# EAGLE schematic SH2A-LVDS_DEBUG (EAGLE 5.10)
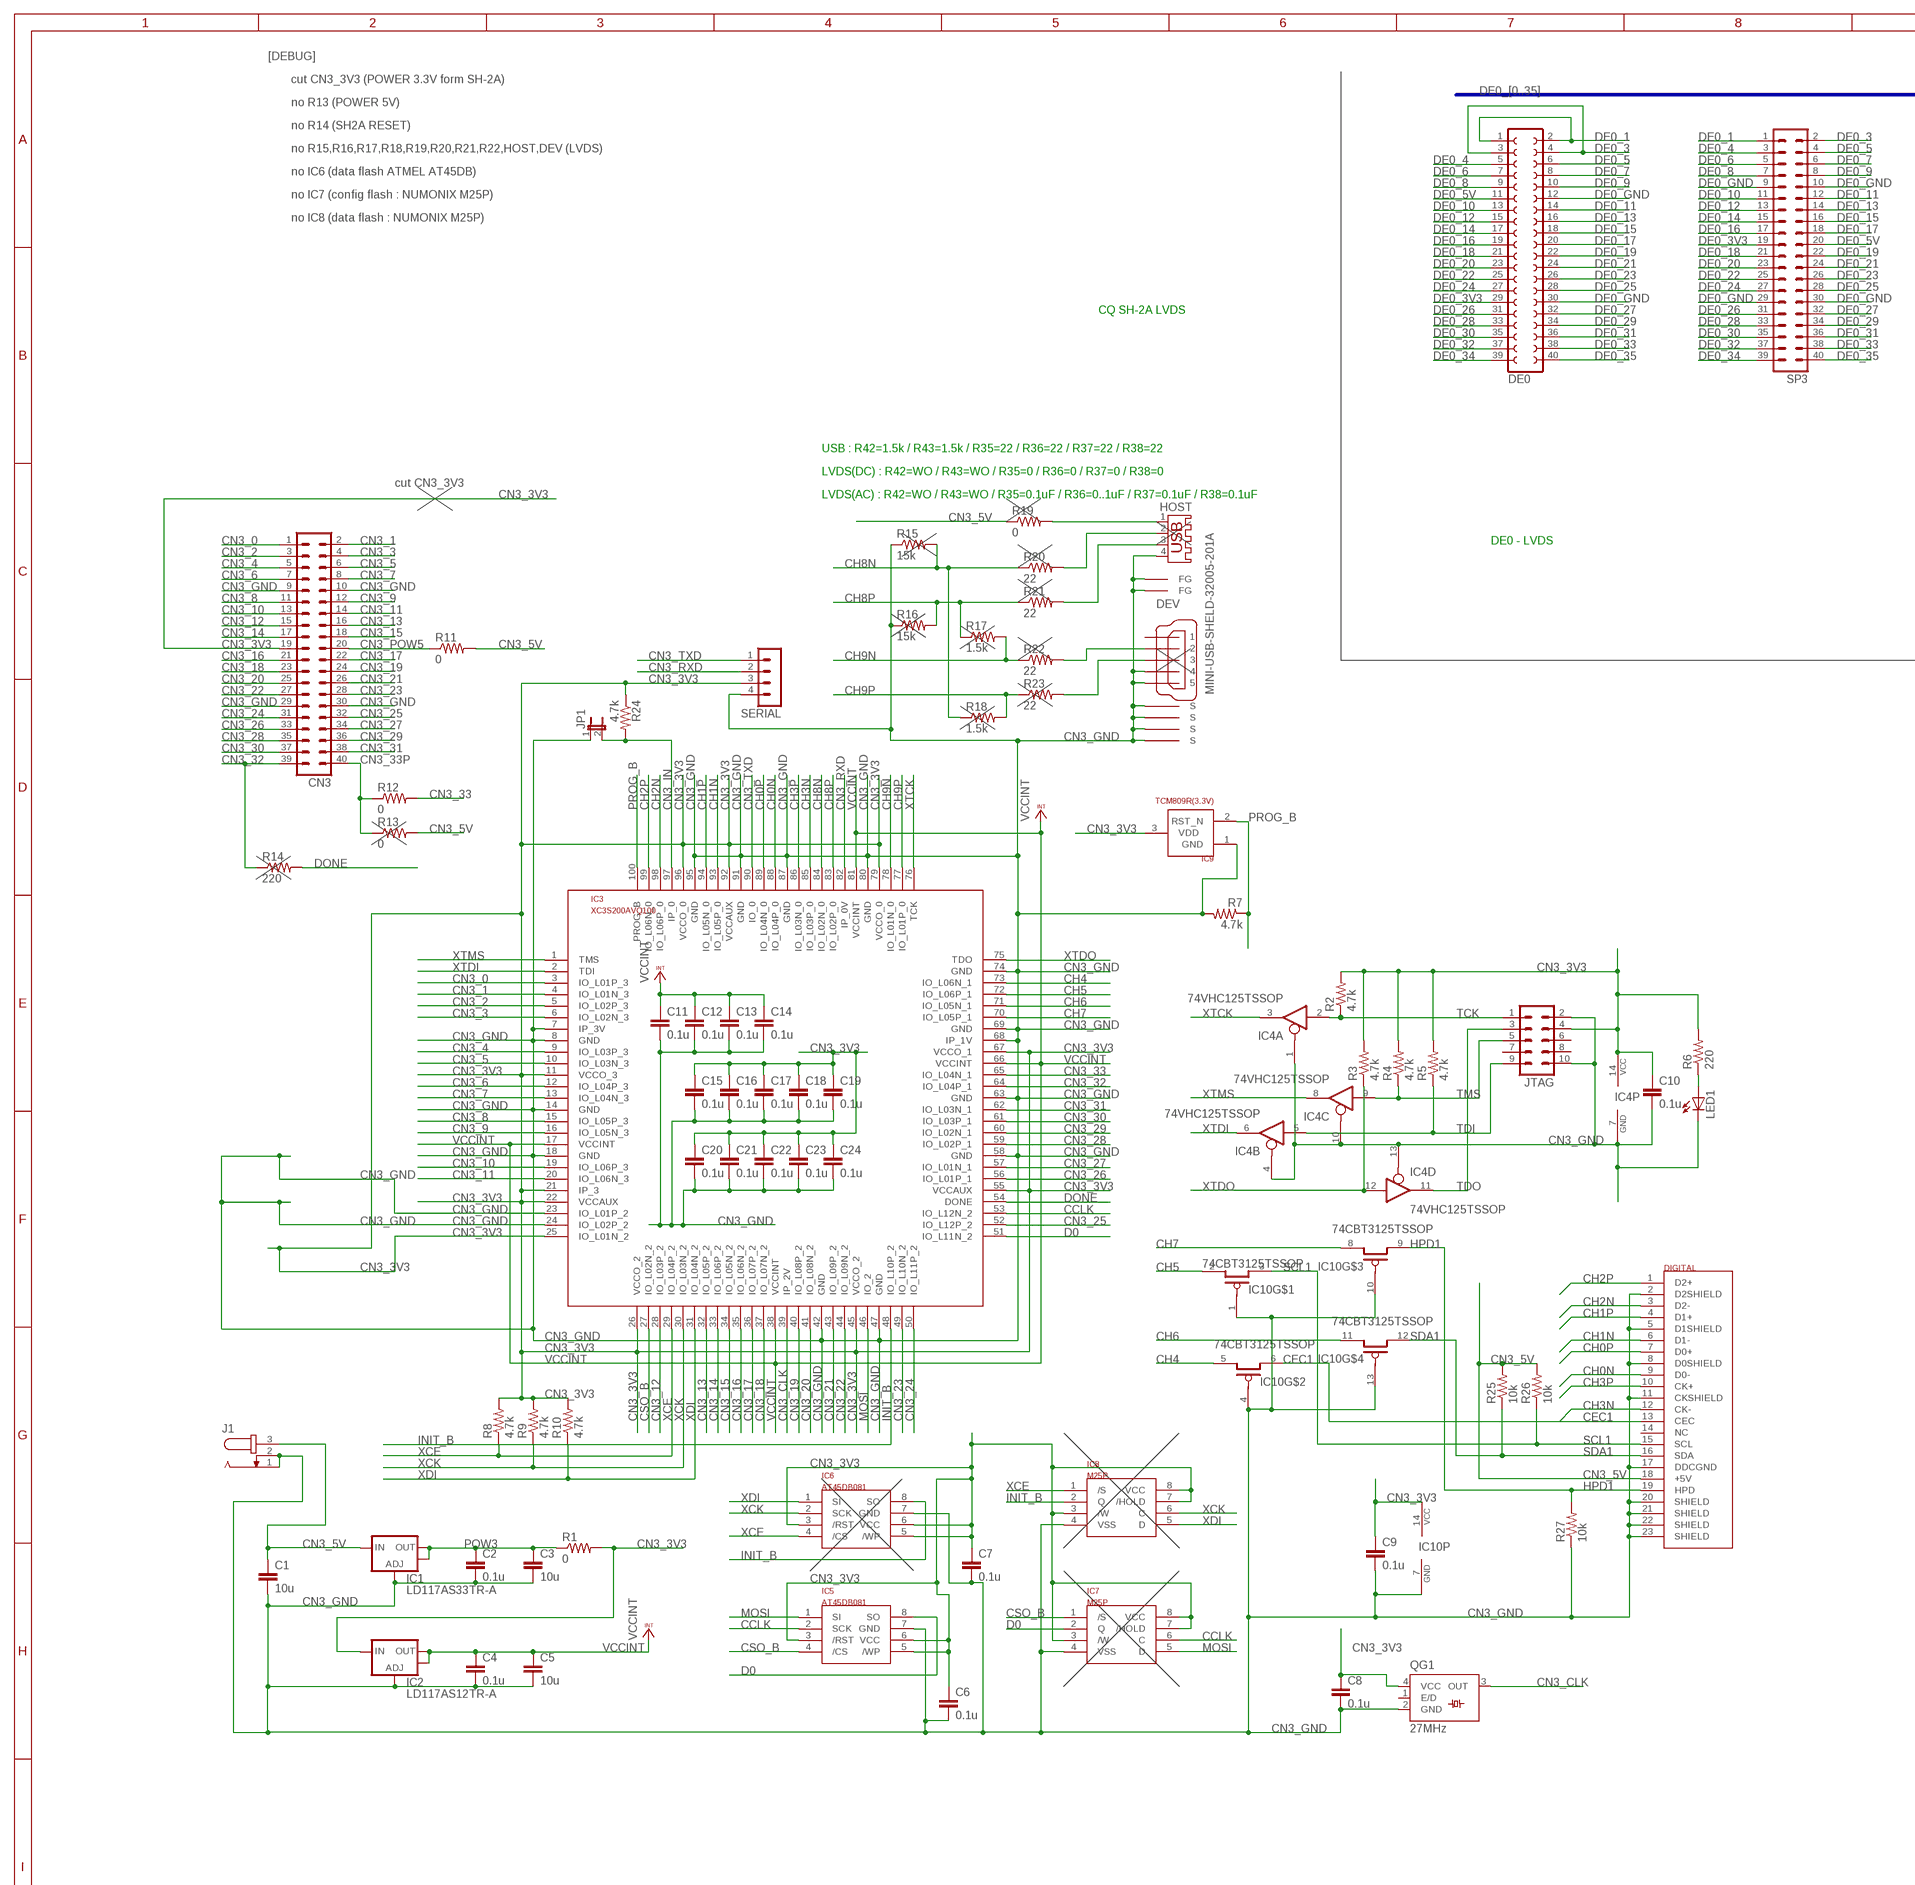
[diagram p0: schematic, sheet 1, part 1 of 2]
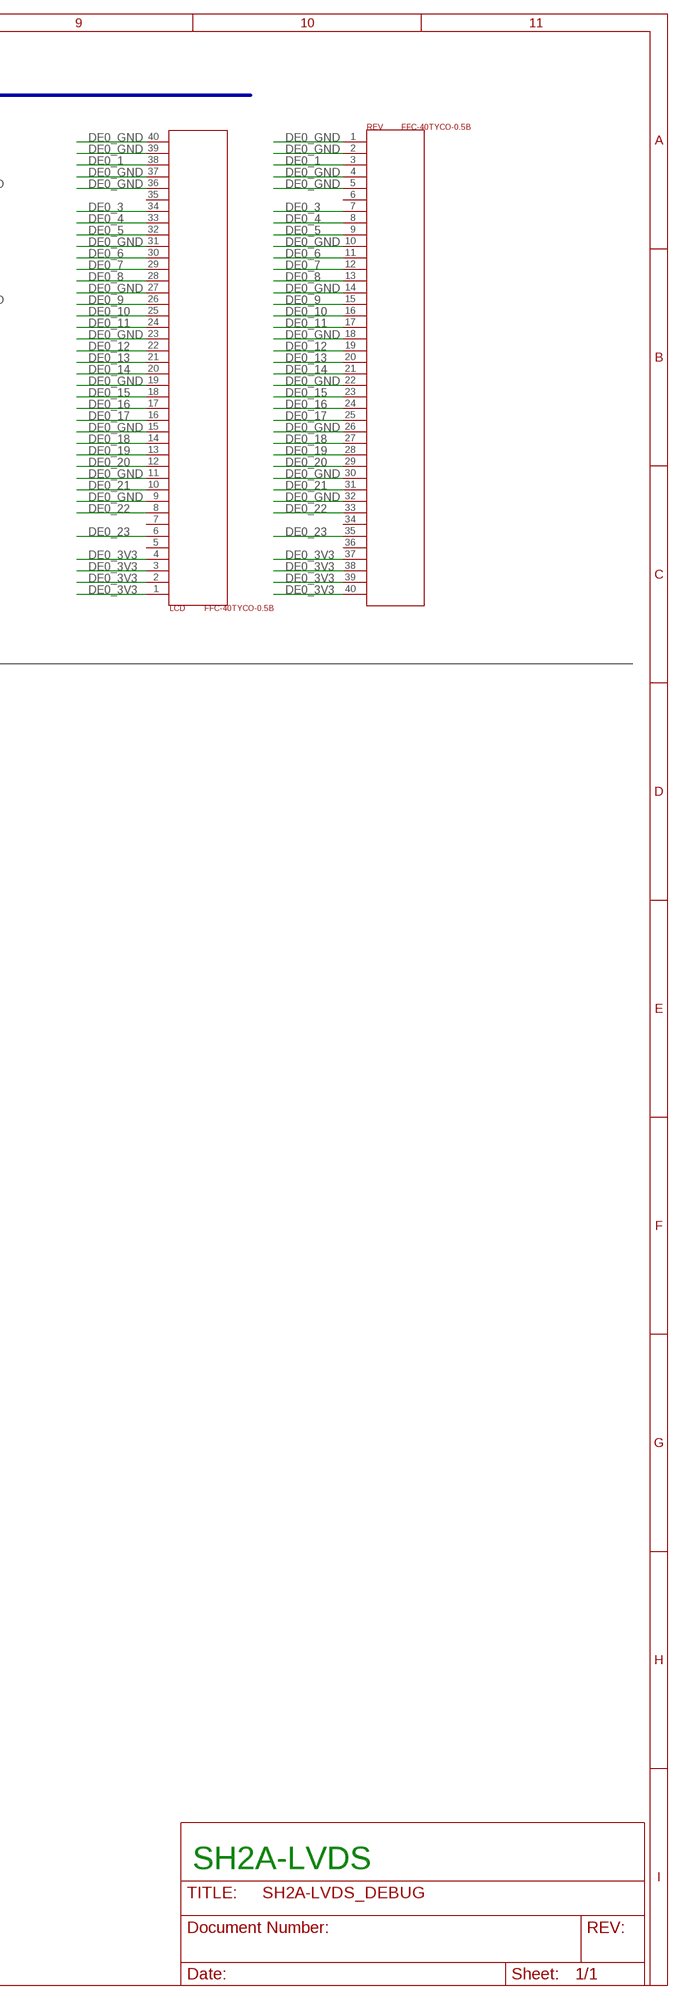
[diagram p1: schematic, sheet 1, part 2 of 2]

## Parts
C1  10u  C-EUC2012  [C2012]
C2  0.1u  C-EUC1608  [C1608]
C3  10u  C-EUC2012  [C2012]
C4  0.1u  C-EUC1608  [C1608]
C5  10u  C-EUC2012  [C2012]
C6  0.1u  C-EUC1608  [C1608]
C7  0.1u  C-EUC1608  [C1608]
C8  0.1u  C-EUC1608  [C1608]
C9  0.1u  C-EUC1608  [C1608]
C10  0.1u  C-EUC1608  [C1608]
C11  0.1u  C-EUC1608  [C1608]
C12  0.1u  C-EUC1608  [C1608]
C13  0.1u  C-EUC1608  [C1608]
C14  0.1u  C-EUC1608  [C1608]
C15  0.1u  C-EUC1608  [C1608]
C16  0.1u  C-EUC1608  [C1608]
C17  0.1u  C-EUC1608  [C1608]
C18  0.1u  C-EUC1608  [C1608]
C19  0.1u  C-EUC1608  [C1608]
C20  0.1u  C-EUC1608  [C1608]
C21  0.1u  C-EUC1608  [C1608]
C22  0.1u  C-EUC1608  [C1608]
C23  0.1u  C-EUC1608  [C1608]
C24  0.1u  C-EUC1608  [C1608]
CN3  MA20-2  [MA20-2]
DE0  FE20-2  [FE20-2]
DEV  MINI-USB-SHELD-32005-201A  [32005-201A]
DIGITAL  HDMIHDMI-FCI-A  [HDMI-FCI-A-UPDATE]
HOST  USB-A003FG  [USB]
IC1  LD117AS33TR-A  LD117AS-A  [SOT223]
IC2  LD117AS12TR-A  LD117AS-A  [SOT223]
IC3  XC3S200AVQ100  XC3S50AVQ100  [VQ100]
IC4  74VHC125TSSOP  74125TSSOP  [PW_R-PDSO-G14]
IC5  AT45DB081  AT45DB  [AT45DB]
IC6  AT45DB081  AT45DB  [AT45DB]
IC7  M25P  [AT45DB]
IC8  M25P  [AT45DB]
IC9  TCM809R(3.3V)  TCM809  [SOT23]
IC10  74CBT3125TSSOP  [PW_R-PDSO-G14]
J1  JACK-PLUG0A  [SPC4077A]
JP1  JP1EA  [JP1A]
JTAG  ML10  [ML10]
LCD  FFC-40TYCO-0.5B  [FFC-40-0.5B-TYCO]
LED1  LED5MM  [LED5MM]
QG1  27MHz  SM77H  [SM77H]
R1  0  R-US_R0603  [R0603]
R2  4.7k  R-US_R0603  [R0603]
R3  4.7k  R-US_R0603  [R0603]
R4  4.7k  R-US_R0603  [R0603]
R5  4.7k  R-US_R0603  [R0603]
R6  220  R-US_R0603  [R0603]
R7  4.7k  R-US_R0603  [R0603]
R8  4.7k  R-US_R0603  [R0603]
R9  4.7k  R-US_R0603  [R0603]
R10  4.7k  R-US_R0603  [R0603]
R11  0  R-US_R0603  [R0603]
R12  0  R-US_R0603  [R0603]
R13  0  R-US_R0603  [R0603]
R14  220  R-US_R0603  [R0603]
R15  15k  R-US_R0603  [R0603]
R16  15k  R-US_R0603  [R0603]
R17  1.5k  R-US_R0603  [R0603]
R18  1.5k  R-US_R0603  [R0603]
R19  0  R-US_R0603  [R0603]
R20  22  R-US_R0603  [R0603]
R21  22  R-US_R0603  [R0603]
R22  22  R-US_R0603  [R0603]
R23  22  R-US_R0603  [R0603]
R24  4.7k  R-US_R0603  [R0603]
R25  10k  R-US_R0603  [R0603]
R26  10k  R-US_R0603  [R0603]
R27  10k  R-US_R0603  [R0603]
REV  FFC-40TYCO-0.5B  [FFC-40-0.5B-TYCO]
SERIAL  MA04-1A  [MA04-1A]
SP3  MA20-2  [MA20-2]

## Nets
CCLK: IC3.53(IO_L12N_2) IC5.2(SCK) IC7.6(C)
CEC1: DIGITAL.13(CEC) IC10.6(O)
CH0N: DIGITAL.9(D0-) IC3.88(IO_L04P_0)
CH0P: DIGITAL.7(D0+) IC3.89(IO_L04N_0)
CH1N: DIGITAL.6(D1-) IC3.93(IO_L05P_0)
CH1P: DIGITAL.4(D1+) IC3.94(IO_L05N_0)
CH2N: DIGITAL.3(D2-) IC3.98(IO_L06P_0)
CH2P: DIGITAL.1(D2+) IC3.99(IO_L06N_0)
CH3N: DIGITAL.12(CK-) IC3.85(IO_L03P_0)
CH3P: DIGITAL.10(CK+) IC3.86(IO_L03N_0)
CH4: IC3.73(IO_L06N_1) IC10.5(I)
CH5: IC3.72(IO_L06P_1) IC10.2(I)
CH6: IC3.71(IO_L05N_1) IC10.11(O)
CH7: IC3.70(IO_L05P_1) IC10.8(O)
CH8N: IC3.84(IO_L02N_0) R15.2 R18.1 R20.1
CH8P: IC3.83(IO_L02P_0) R16.2 R17.1 R21.1
CH9N: IC3.78(IO_L01N_0) R17.2 R22.1
CH9P: IC3.77(IO_L01P_0) R18.2 R23.1
CN3_0: CN3.1 IC3.3(IO_L01P_3)
CN3_1: CN3.2 IC3.4(IO_L01N_3)
CN3_2: CN3.3 IC3.5(IO_L02P_3)
CN3_3: CN3.4 IC3.6(IO_L02N_3)
CN3_3V3: C6.1 C7.1 C8.1 C9.1 C10.1 C15.1 C16.1 C17.1 C18.1 C19.1 C20.1 C21.1 C22.1 C23.1 C24.1 CN3.19 IC2.3(IN) IC3.11(VCCO_3) IC3.21(IP_3) IC3.22(VCCAUX) IC3.25(IO_L01N_2) IC3.26(VCCO_2) IC3.45(VCCO_2) IC3.55(VCCAUX) IC3.67(VCCO_1) IC3.79(VCCO_0) IC3.92(VCCAUX) IC3.96(VCCO_0) IC4.14(P:VCC) IC5.3(/RST) IC5.5(/WP) IC5.6(VCC) IC6.3(/RST) IC6.5(/WP) IC6.6(VCC) IC7.3(/W) IC7.7(/HOLD) IC7.8(VCC) IC8.3(/W) IC8.7(/HOLD) IC8.8(VCC) IC9.3(VDD) IC10.14(P:VCC) JTAG.4 QG1.4(VCC) R1.2 R2.2 R3.2 R4.2 R5.2 R6.2 R8.2 R9.2 R10.2 R24.1 SERIAL.3
CN3_4: CN3.5 IC3.9(IO_L03P_3)
CN3_5: CN3.6 IC3.10(IO_L03N_3)
CN3_5V: C1.1 DIGITAL.18(+5V) IC1.3(IN) J1.3 R11.2 R13.2 R19.1 R25.2 R26.2
CN3_6: CN3.7 IC3.12(IO_L04P_3)
CN3_7: CN3.8 IC3.13(IO_L04N_3)
CN3_8: CN3.11 IC3.15(IO_L05P_3)
CN3_9: CN3.12 IC3.16(IO_L05N_3)
CN3_10: CN3.13 IC3.19(IO_L06P_3)
CN3_11: CN3.14 IC3.20(IO_L06N_3)
CN3_12: CN3.15 IC3.28(IO_L03P_2)
CN3_13: CN3.16 IC3.32(IO_L05P_2)
CN3_14: CN3.17 IC3.33(IO_L06P_2)
CN3_15: CN3.18 IC3.34(IO_L05N_2)
CN3_16: CN3.21 IC3.35(IO_L06N_2)
CN3_17: CN3.22 IC3.36(IO_L07P_2)
CN3_18: CN3.23 IC3.37(IO_L07N_2)
CN3_19: CN3.24 IC3.40(IO_L08P_2)
CN3_20: CN3.25 IC3.41(IO_L08N_2)
CN3_21: CN3.26 IC3.43(IO_L09P_2)
CN3_22: CN3.27 IC3.44(IO_L09N_2)
CN3_23: CN3.28 IC3.49(IO_L10N_2)
CN3_24: CN3.31 IC3.50(IO_L11P_2)
CN3_25: CN3.32 IC3.52(IO_L12P_2)
CN3_26: CN3.33 IC3.56(IO_L01P_1)
CN3_27: CN3.34 IC3.57(IO_L01N_1)
CN3_28: CN3.35 IC3.59(IO_L02P_1)
CN3_29: CN3.36 IC3.60(IO_L02N_1)
CN3_30: CN3.37 IC3.61(IO_L03P_1)
CN3_31: CN3.38 IC3.62(IO_L03N_1)
CN3_32: CN3.39 IC3.64(IO_L04P_1) R14.1
CN3_33: IC3.65(IO_L04N_1) R12.2
CN3_33P: CN3.40 R12.1 R13.1
CN3_CLK: IC3.39(IP_2V) QG1.3(OUT)
CN3_GND: C1.2 C2.2 C3.2 C4.2 C5.2 C6.2 C7.2 C8.2 C9.2 C10.2 C11.2 C12.2 C13.2 C14.2 C15.2 C16.2 C17.2 C18.2 C19.2 C20.2 C21.2 C22.2 C23.2 C24.2 CN3.9 CN3.10 CN3.29 CN3.30 DEV.4 DEV.5 DEV.M1(S) DEV.M2(S) DEV.M3(S) DEV.M4(S) DIGITAL.2(D2SHIELD) DIGITAL.5(D1SHIELD) DIGITAL.8(D0SHIELD) DIGITAL.11(CKSHIELD) DIGITAL.17(DDCGND) DIGITAL.20(SHIELD) DIGITAL.21(SHIELD) DIGITAL.22(SHIELD) DIGITAL.23(SHIELD) HOST.4 HOST.P$1(FG) HOST.P$2(FG) IC1.1(ADJ) IC2.1(ADJ) IC3.7(IP_3V) IC3.8(GND) IC3.14(GND) IC3.18(GND) IC3.23(IO_L01P_2) IC3.24(IO_L02P_2) IC3.42(GND) IC3.47(GND) IC3.58(GND) IC3.63(GND) IC3.68(IP_1V) IC3.69(GND) IC3.74(GND) IC3.80(GND) IC3.87(GND) IC3.91(GND) IC3.95(GND) IC4.1(A:OE) IC4.4(B:OE) IC4.7(P:GND) IC4.10(C:OE) IC4.13(D:OE) IC5.7(GND) IC6.7(GND) IC7.4(VSS) IC8.4(VSS) IC9.1(GND) IC10.1(OE) IC10.4(OE) IC10.7(P:GND) IC10.10(OE) IC10.13(OE) J1.1 J1.2 JP1.1 JTAG.2 JTAG.10 LED1.K(C) QG1.2(GND) R7.2 R15.1 R16.1 R27.1 SERIAL.4
CN3_IN: IC3.97(IP_0) JP1.2 R24.2
CN3_POW5: CN3.20 R11.1
CN3_RXD: IC3.82(IP_0V) SERIAL.2
CN3_TXD: IC3.90(IO_0) SERIAL.1
CSO_B: IC3.27(IO_L02N_2) IC5.4(/CS) IC7.1(/S)
D0: IC3.51(IO_L11N_2) IC5.8(SO) IC7.2(Q)
DE0_1: DE0.1 DE0.2 LCD.38 REV.3 SP3.1
DE0_3: DE0.3 DE0.4 LCD.34 REV.7 SP3.2
DE0_3V3: DE0.29 LCD.1 LCD.2 LCD.3 LCD.4 REV.37 REV.38 REV.39 REV.40 SP3.19
DE0_4: DE0.5 LCD.33 REV.8 SP3.3
DE0_5: DE0.6 LCD.32 REV.9 SP3.4
DE0_5V: DE0.11 SP3.20
DE0_6: DE0.7 LCD.30 REV.11 SP3.5
DE0_7: DE0.8 LCD.29 REV.12 SP3.6
DE0_8: DE0.9 LCD.28 REV.13 SP3.7
DE0_9: DE0.10 LCD.26 REV.15 SP3.8
DE0_10: DE0.13 LCD.25 REV.16 SP3.11
DE0_11: DE0.14 LCD.24 REV.17 SP3.12
DE0_12: DE0.15 LCD.22 REV.19 SP3.13
DE0_13: DE0.16 LCD.21 REV.20 SP3.14
DE0_14: DE0.17 LCD.20 REV.21 SP3.15
DE0_15: DE0.18 LCD.18 REV.23 SP3.16
DE0_16: DE0.19 LCD.17 REV.24 SP3.17
DE0_17: DE0.20 LCD.16 REV.25 SP3.18
DE0_18: DE0.21 LCD.14 REV.27 SP3.21
DE0_19: DE0.22 LCD.13 REV.28 SP3.22
DE0_20: DE0.23 LCD.12 REV.29 SP3.23
DE0_21: DE0.24 LCD.10 REV.31 SP3.24
DE0_22: DE0.25 LCD.8 REV.33 SP3.25
DE0_23: DE0.26 LCD.6 REV.35 SP3.26
DE0_24: DE0.27 SP3.27
DE0_25: DE0.28 SP3.28
DE0_26: DE0.31 SP3.31
DE0_27: DE0.32 SP3.32
DE0_28: DE0.33 SP3.33
DE0_29: DE0.34 SP3.34
DE0_30: DE0.35 SP3.35
DE0_31: DE0.36 SP3.36
DE0_32: DE0.37 SP3.37
DE0_33: DE0.38 SP3.38
DE0_34: DE0.39 SP3.39
DE0_35: DE0.40 SP3.40
DE0_GND: DE0.12 DE0.30 LCD.9 LCD.11 LCD.15 LCD.19 LCD.23 LCD.27 LCD.31 LCD.36 LCD.37 LCD.39 LCD.40 REV.1 REV.2 REV.4 REV.5 REV.10 REV.14 REV.18 REV.22 REV.26 REV.30 REV.32 SP3.9 SP3.10 SP3.29 SP3.30
DONE: IC3.54(DONE) R14.2
HPD1: DIGITAL.19(HPD) IC10.9(I) R27.2
INIT_B: IC3.48(IO_L10P_2) IC6.8(SO) IC8.2(Q)
MOSI: IC3.46(IO_2) IC5.1(SI) IC7.5(D)
N$2: HOST.1 R19.2
N$4: HOST.2 R20.2
N$5: HOST.3 R21.2
N$6: DEV.2 R22.2
N$9: DEV.3 R23.2
N$10: LED1.A R6.1
POW3: C2.1 C3.1 IC1.2(OUT) IC1.4(OUT) R1.1
PROG_B: IC3.100(PROG_B) IC9.2(RST_N) R7.1
SCL1: DIGITAL.15(SCL) IC10.3(O) R26.1
SDA1: DIGITAL.16(SDA) IC10.12(I) R25.1
TCK: IC4.2(A:I) JTAG.1 R2.1
TDI: IC4.5(B:I) JTAG.9 R5.1
TDO: IC4.11(D:O) JTAG.3
TMS: IC4.9(C:I) JTAG.5 R4.1
VCCINT: C4.1 C5.1 C11.1 C12.1 C13.1 C14.1 IC2.2(OUT) IC2.4(OUT) IC3.17(VCCINT) IC3.38(VCCINT) IC3.66(VCCINT) IC3.81(VCCINT)
XCE: IC3.29(IO_L04P_2) IC6.4(/CS) IC8.1(/S) R8.1
XCK: IC3.30(IO_L03N_2) IC6.2(SCK) IC8.6(C) R9.1
XDI: IC3.31(IO_L04N_2) IC6.1(SI) IC8.5(D) R10.1
XTCK: IC3.76(TCK) IC4.3(A:O)
XTDI: IC3.2(TDI) IC4.6(B:O)
XTDO: IC3.75(TDO) IC4.12(D:I) R3.1
XTMS: IC3.1(TMS) IC4.8(C:O)
Unconnected: DEV.1 DIGITAL.14(NC) JTAG.6 JTAG.7 JTAG.8 LCD.5 LCD.7 LCD.35 QG1.1(E/D) REV.6 REV.34 REV.36

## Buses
DE0_[0..35]

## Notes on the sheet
- [DEBUG]
- cut CN3_3V3 (POWER 3.3V form SH-2A)
- no R13 (POWER 5V)
- no R14 (SH2A RESET)
- no R15,R16,R17,R18,R19,R20,R21,R22,HOST,DEV (LVDS)
- no IC6 (data flash ATMEL AT45DB)
- no IC7 (config flash : NUMONIX M25P)
- no IC8 (data flash : NUMONIX M25P)
- CQ SH-2A LVDS
- USB : R42=1.5k / R43=1.5k / R35=22 / R36=22 / R37=22 / R38=22
- LVDS(DC) : R42=WO / R43=WO / R35=0 / R36=0 / R37=0 / R38=0
- cut CN3_3V3
- LVDS(AC) : R42=WO / R43=WO / R35=0.1uF / R36=0..1uF / R37=0.1uF / R38=0.1uF
- DE0 - LVDS
- SH2A-LVDS

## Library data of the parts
C1-C24 = adcr:C-EU: CAPACITOR, European symbol
CN3 SP3 = adcr:MA20-2: PIN HEADER
DE0 = con-lsta:FE20-2: FEMALE HEADER
DEV = adcr:MINI-USB-SHELD-
DIGITAL = adcr:HDMI
HOST = adcr:USB-A003: USB connector
IC1 IC2 = adcr:LD117A?*-A
IC3 = adcr:XC3S50AVQ100
IC4 = adcr:74*125: Quad bus BUFFER, 3-state
IC5 IC6 = adcr:AT45DB
IC7 IC8 = adcr:M25P
IC9 = adcr:TCM809
IC10 = adcr:74CBT3125
J1 = adcr:JACK-PLUG: DC POWER JACK Power Jack, DC, Right Angle, Through Hole, Rated 5A at 16VDC, PC Terminals Distributor: Farnell (www.Farnell.de) Drawing: 84N1161.pdf / 84N1162.pdf Manufacturer: SPC Technology (www.spctechnology.com) Type: SPC4077 / SPC 4078
JP1 = adcr:JP1E: JUMPER
JTAG = con-ml:ML10: HARTING
LCD REV = adcr:FFC-40
LED1 = adcr:LED: LED
QG1 = adcr:SM77H: 3.3V CMOS Clock Oscillator Source: www.pletronics.com .. sm77h%203.3v.pdf
R1-R27 = adcr:R-US_: RESISTOR, American symbol
SERIAL = adcr:MA04-1: PIN HEADER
